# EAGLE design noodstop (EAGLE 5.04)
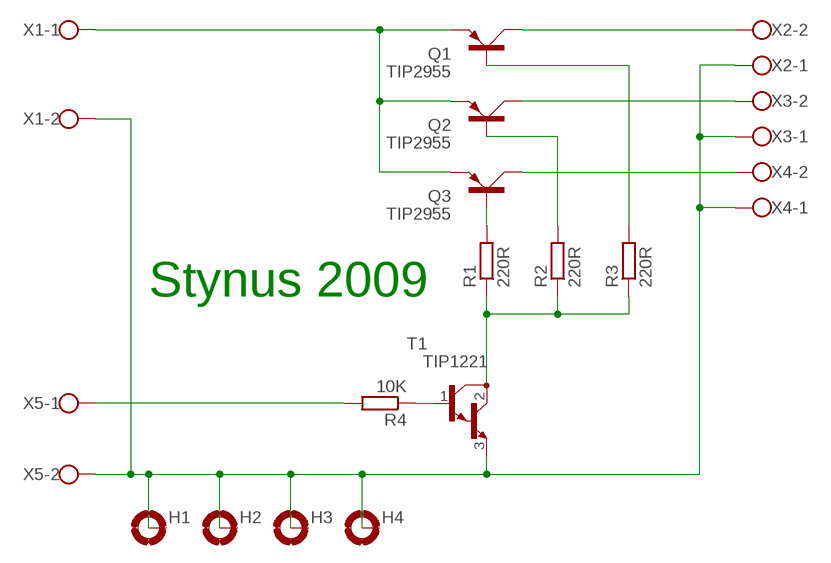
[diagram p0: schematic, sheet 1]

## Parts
H1  MOUNT-PAD-ROUND3.0  [3,0-PAD]
H2  MOUNT-PAD-ROUND3.0  [3,0-PAD]
H3  MOUNT-PAD-ROUND3.0  [3,0-PAD]
H4  MOUNT-PAD-ROUND3.0  [3,0-PAD]
Q1  TIP2955  [TOP3AV]
Q2  TIP2955  [TOP3AV]
Q3  TIP2955  [TOP3AV]
R1  220R  R-EU_0617/22  [0617/22]
R2  220R  R-EU_0617/22  [0617/22]
R3  220R  R-EU_0617/22  [0617/22]
R4  10K  R-EU_0204/7  [0204/7]
T1  TIP1221  [TO220AV]
X1  W237-02P  [W237-132]
X2  W237-02P  [W237-132]
X3  W237-02P  [W237-132]
X4  W237-02P  [W237-132]
X5  W237-02P  [W237-132]

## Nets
GND: H1.B3,0(MOUNT) H2.B3,0(MOUNT) H3.B3,0(MOUNT) H4.B3,0(MOUNT) T1.3(E) X1.2 X2.1 X3.1 X4.1 X5.2
N$2: Q3.B R1.2
N$3: Q2.B R2.2
N$4: Q1.B R3.2
N$5: R1.1 R2.1 R3.1 T1.2(C)
N$6: R4.1 T1.1(B)
N$7: R4.2 X5.1
N$8: Q1.E Q2.E Q3.E X1.1
N$9: Q1.C X2.2
N$10: Q2.C X3.2
N$11: Q3.C X4.2

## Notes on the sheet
- Stynus 2009

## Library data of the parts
H1-H4 = holes:MOUNT-PAD-ROUND: MOUNTING PAD, round
Q1-Q3 = transistor-power:TIP2955: PNP TRANSISTOR
R1-R4 = rcl:R-EU_: RESISTOR, European symbol
T1 = transistor:TIP122: NPN BIPOLAR DARLINGTON TRANSISTOR
X1-X5 = con-wago-508:W237-02P: WAGO SREW CLAMP

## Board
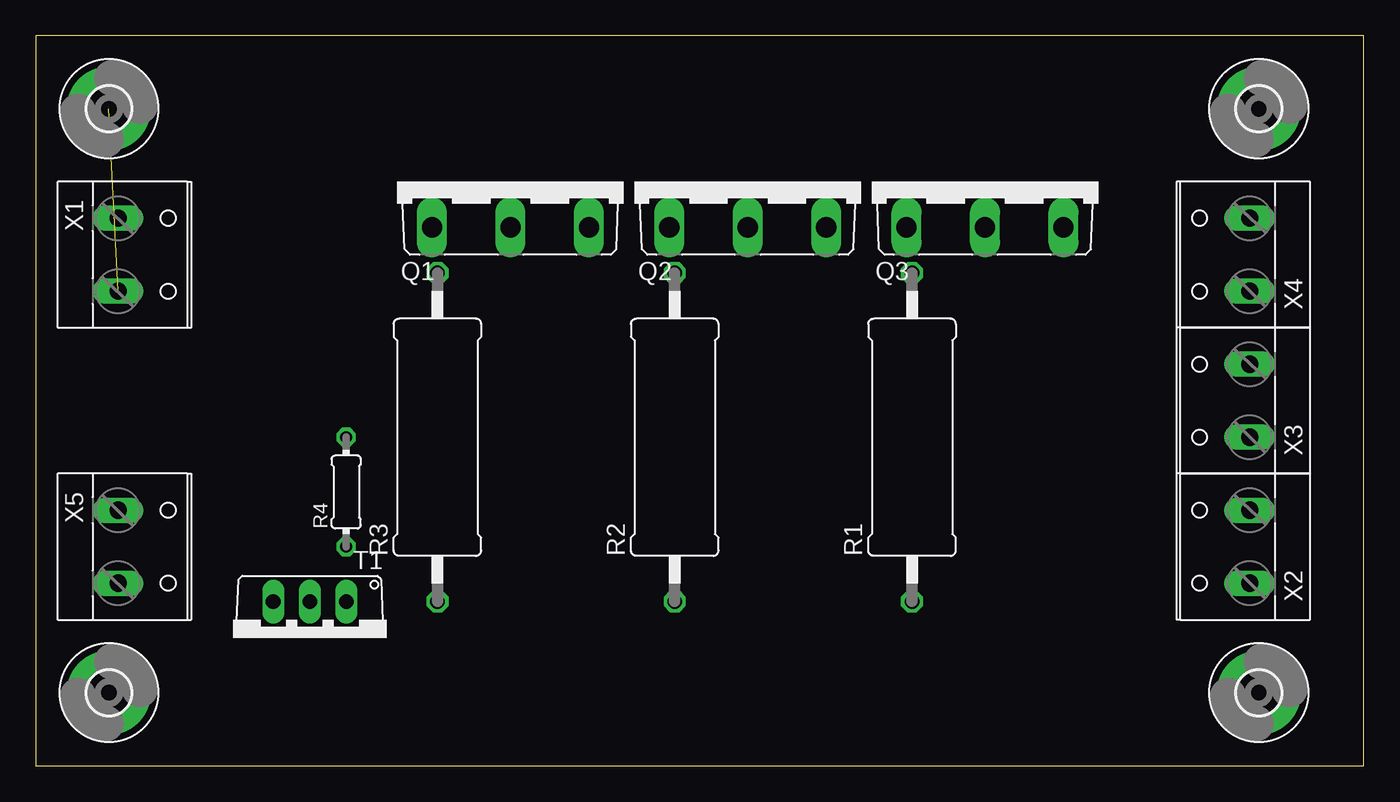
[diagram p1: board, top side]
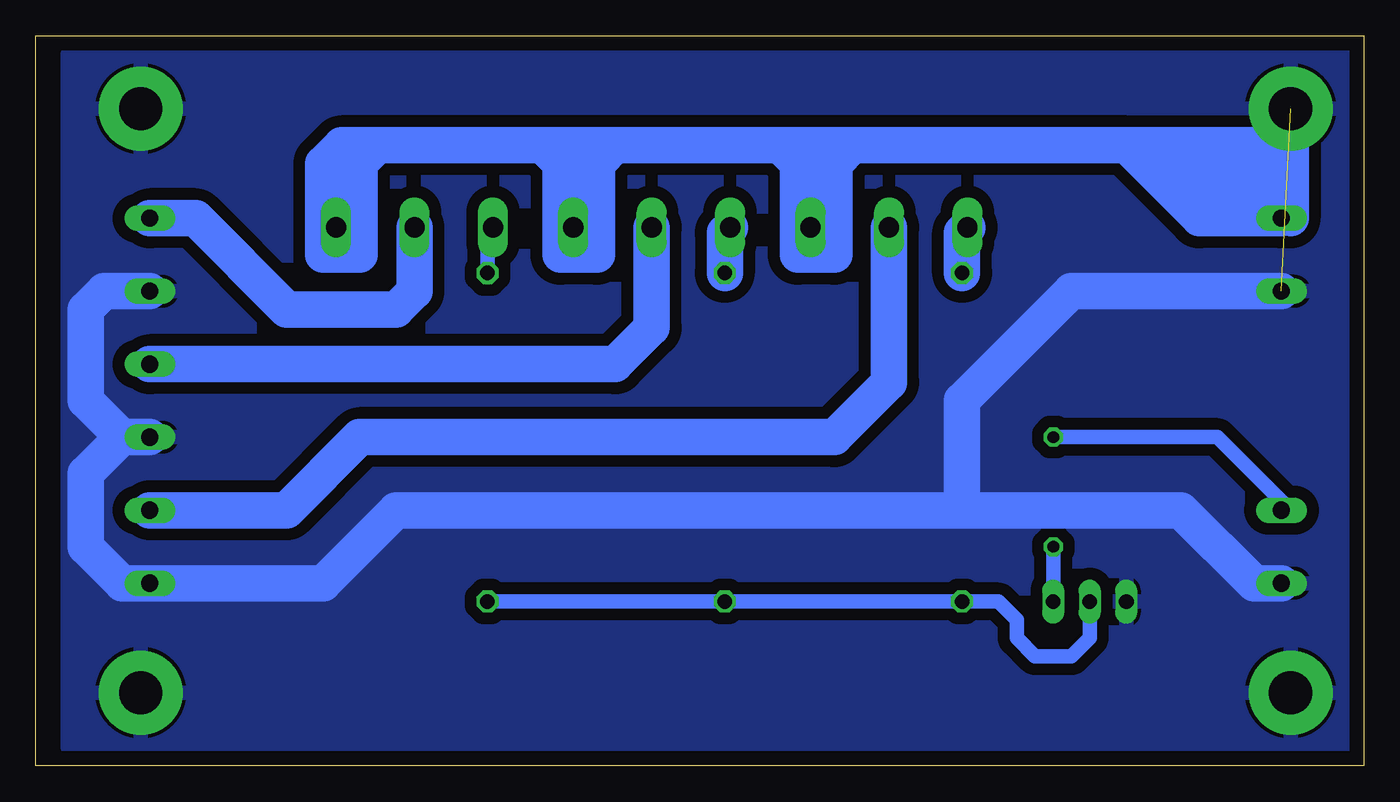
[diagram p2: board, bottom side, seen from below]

Size 92.38 x 50.79 mm. Coordinates in mm from the lower left corner, seen from the top.
Outline: 0,0 92.38,0 92.38,50.79 0,50.79 0,0
Copper layers (1*16): Top 0.035mm / dielectric 1.5mm / Bottom 0.035mm
Design rules "default": minimum track width 10mil, minimum drill 24mil, track to track 8mil, track to pad 8mil, pad to pad 8mil, via to via 8mil, smd to smd 8mil, copper to edge 40mil, drill to drill 8mil, minimum pad ring 10mil, minimum via ring 8mil, stop-mask expansion 4mil, vias tented up to drill 0mil, thermal gap 10mil

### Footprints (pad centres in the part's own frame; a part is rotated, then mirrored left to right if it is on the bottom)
3,0-PAD = drill 3 pad 5.842 round: B3,0 0,0
TOP3AV = drill 1.397 long: B -5.461,-3.175; C 0,-3.175; E 5.461,-3.175
0617/22 = drill 1.016 octagon: 1 -11.43,0; 2 11.43,0
0204/7 = drill 0.813 octagon: 1 -3.81,0; 2 3.81,0
TO220AV = drill 1.016 long: 1 -2.54,-2.54; 2 0,-2.54; 3 2.54,-2.54
W237-132 = drill 1.194 long: 1 -2.54,-0.635; 2 2.54,-0.635

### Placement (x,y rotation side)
H1  5.08,5.08 0 top
H2  85.09,5.08 0 top
H3  5.08,45.72 0 top
H4  85.09,45.72 0 top
Q1  33.02,40.64 0 top
Q2  49.53,40.64 0 top
Q3  66.04,40.64 0 top
R1  60.96,22.86 90 top
R2  44.45,22.86 90 top
R3  27.94,22.86 90 top
R4  21.59,19.05 90 top
T1  19.05,8.89 180 top
X1  6.35,35.56 270 top
X2  83.82,15.24 90 top
X3  83.82,25.4 90 top
X4  83.82,35.56 90 top
X5  6.35,15.24 270 top

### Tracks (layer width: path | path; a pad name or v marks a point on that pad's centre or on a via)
GND  (1 unrouted)
  Bottom 2.54: 86.36,22.86 88.9,20.32 88.9,15.24 86.36,12.7 X2.1 72.39,12.7 67.31,17.78 27.94,17.78 | 86.36,22.86 X3.1 | X4.1 87.63,33.02 88.9,31.75 88.9,25.4 86.36,22.86 | X5.2 7.62,12.7 12.7,17.78 27.94,17.78 | X1.2 20.32,33.02 27.94,25.4 27.94,17.78
  pour Bottom (isolate 0.813): 1.27,49.53 90.17,49.53 90.17,1.27 1.27,1.27
N$2
  Bottom 1.016: Q3.B 60.96,37.47 R1.2
N$3
  Bottom 2.54: R2.2 44.45,37.08 Q2.B
N$4
  Bottom 2.54: R3.2 27.94,37.08 Q1.B
N$5
  Bottom 1.016: R1.1 R2.1 R3.1 25.4,11.43 24.13,10.16 24.13,8.89 22.86,7.62 20.32,7.62 19.05,8.89 T1.2
N$6
  Bottom 1.016: T1.1 R4.1
N$7
  Bottom 1.016: R4.2 10.16,22.86 5.08,17.78 X5.1
N$8
  Bottom 1.016: Q2.E 54.61,37.47 54.61,39.37
  Bottom 2.54: 5.08,38.1 5.08,43.18 10.16,43.18 | 69.85,39.37 69.85,40.64 | 69.85,39.37 69.85,35.56 72.39,35.56 | 72.39,35.56 72.39,41.91 71.12,43.18 67.31,43.18 | X1.1 11.43,38.1 16.51,43.18 | 16.51,43.18 35.56,43.18 | 35.56,43.18 38.1,40.64 | 38.1,40.64 38.1,41.66 Q1.E | 69.85,41.91 71.5,40.26 | 53.34,43.18 54.61,43.18 | 38.1,40.64 39.37,41.91 | 57.15,43.18 67.31,43.18 | 54.61,43.18 57.15,43.18 | 54.61,43.18 54.61,39.37 54.61,37.85 | 35.56,43.18 36.83,41.91 36.83,35.56 39.37,35.56 39.37,41.91 | 35.56,43.18 40.64,43.18 | 40.64,43.18 39.37,41.91 | 57.15,43.18 55.88,41.91 55.88,35.56 53.34,35.56 53.34,41.91 52.07,43.18 | 53.34,43.18 57.15,43.18 | 40.64,43.18 52.07,43.18 | 52.07,43.18 53.34,43.18 | 67.31,43.18 68.58,43.18 69.85,41.91 | 69.85,41.91 69.85,39.37 | 16.51,43.18 10.16,43.18 | 16.51,43.18 13.97,43.18 10.16,39.37 7.62,39.37 6.35,40.64 7.62,41.91 8.89,41.91 10.16,40.64 | 10.16,43.18 11.43,41.91 | Q3.E 71.5,36.45 72.39,35.56
N$9
  Bottom 2.54: X2.2 74.93,17.78 69.85,22.86 36.83,22.86 33.02,26.67 Q1.C
N$10
  Bottom 2.54: X3.2 52.07,27.94 49.53,30.48 Q2.C
N$11
  Bottom 2.54: X4.2 81.28,38.1 74.93,31.75 67.31,31.75 66.04,33.02 Q3.C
